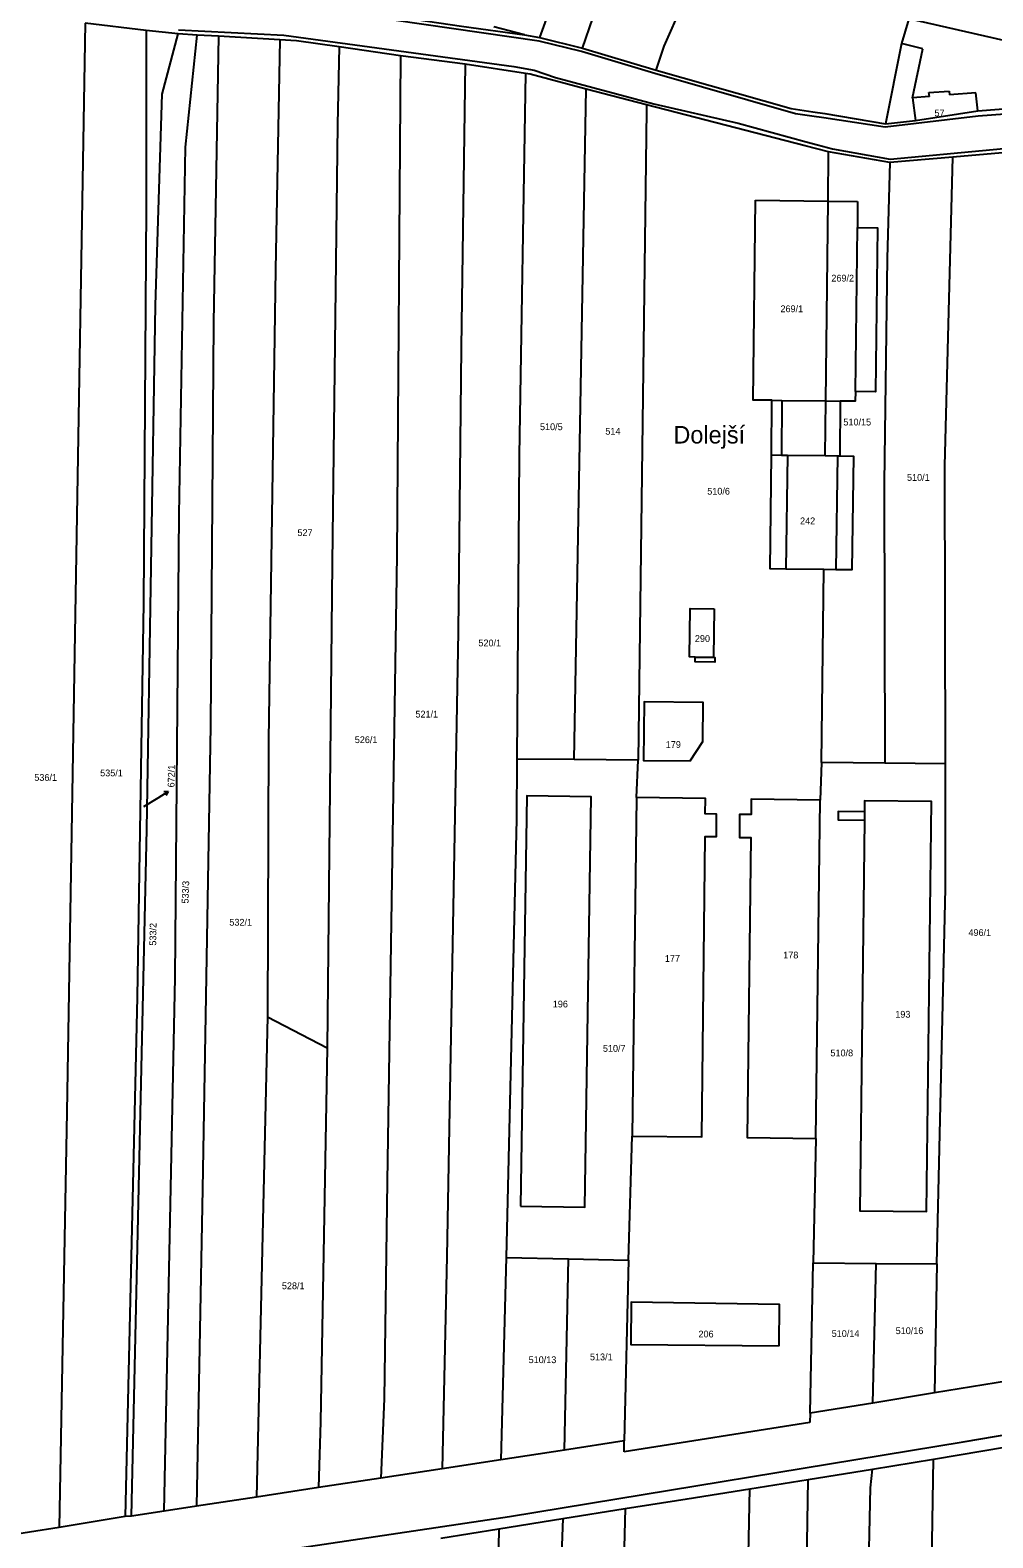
# Model space of a CAD drawing. Extents: x -7483133 to -743169, y -11317770 to -1127091.
# Drawn here: x -746642.5 to -746401, y -1132680.7 to -1132302.3 of the extents above; entities that cross this region are included whole.
import ezdxf

# ---------------------------------------------------------------- set-up
doc = ezdxf.new("R2010")
doc.units = 0
for name, color, linetype in [('Hranice parcel', 7, 'Continuous'), ('Parcelní čísla', 7, 'Continuous'), ('Pop  PČ popisy', 7, 'Continuous'), ('Vnitřní kresba', 7, 'Continuous')]:
    doc.layers.add(name, color=color, linetype=linetype)

msp = doc.modelspace()

# ---------------------------------------------------------------- linework, layer by layer
at = {"layer": 'Hranice parcel'}
for p, q in [((-746503.94, -1132306.81), (-746501.31, -1132299.32)), ((-746398.2, -1132304.9), (-746422.09, -1132299.47)), ((-746613.37, -1132302.42), (-746628.68, -1132300.58)), ((-746605.37, -1132303.28), (-746613.37, -1132302.42)), ((-746600.59, -1132303.55), (-746605.37, -1132303.28)), ((-746518.52, -1132303.5), (-746526.21, -1132301.5)), ((-746518.52, -1132303.5), (-746514.75, -1132304.17)), ((-746595.23, -1132303.86), (-746600.59, -1132303.55)), ((-746579.9, -1132304.75), (-746595.23, -1132303.86)), ((-746549.55, -1132308.74), (-746564.99, -1132306.52)), ((-746514.75, -1132304.17), (-746503.94, -1132306.81)), ((-746503.94, -1132306.81), (-746485.44, -1132312.39)), ((-746533.39, -1132310.87), (-746549.55, -1132308.74)), ((-746518.2, -1132313.24), (-746533.39, -1132310.87)), ((-746506, -1132485.37), (-746503.02, -1132317.1)), ((-746487.88, -1132321.09), (-746503.02, -1132317.1)), ((-746487.88, -1132321.09), (-746487.9, -1132322.49)), ((-746448.07, -1132331.38), (-746487.88, -1132321.09)), ((-746487.9, -1132322.49), (-746489.99, -1132485.51)), ((-746445.16, -1132332.13), (-746448.07, -1132331.38)), ((-746442.17, -1132332.88), (-746445.16, -1132332.13)), ((-746442.31, -1132345.22), (-746442.17, -1132332.88)), ((-746426.85, -1132335.55), (-746442.17, -1132332.88)), ((-746392.82, -1132332.59), (-746411.01, -1132334.18)), ((-746411.01, -1132334.18), (-746426.85, -1132335.55)), ((-746460.56, -1132344.98), (-746442.31, -1132345.22)), ((-746442.31, -1132345.22), (-746434.93, -1132345.32)), ((-746452.53, -1132408.97), (-746443.06, -1132409.09)), ((-746443.06, -1132409.09), (-746439.94, -1132409.14)), ((-746439.94, -1132409.14), (-746439.38, -1132409.16)), ((-746443.39, -1132437.7), (-746452.91, -1132437.58)), ((-746443.96, -1132486.07), (-746443.39, -1132437.7)), ((-746440.33, -1132437.74), (-746443.39, -1132437.7)), ((-746506, -1132485.37), (-746520.37, -1132485.24)), ((-746489.99, -1132485.51), (-746506, -1132485.37)), ((-746490.36, -1132494.89), (-746489.99, -1132485.51)), ((-746443.96, -1132486.07), (-746444.3, -1132495.53)), ((-746428.08, -1132486.27), (-746443.96, -1132486.07)), ((-746412.82, -1132486.47), (-746428.08, -1132486.27)), ((-746490.36, -1132494.89), (-746491.44, -1132579.84)), ((-746445.35, -1132580.44), (-746444.3, -1132495.53)), ((-746582.99, -1132549.96), (-746585.75, -1132670.43)), ((-746582.99, -1132549.96), (-746568.01, -1132557.67)), ((-746492.38, -1132610.98), (-746491.44, -1132579.84)), ((-746445.35, -1132580.44), (-746446.07, -1132611.66)), ((-746523.05, -1132610.33), (-746524.45, -1132661.07)), ((-746523.05, -1132610.33), (-746507.48, -1132610.66)), ((-746508.44, -1132658.63), (-746507.48, -1132610.66)), ((-746507.48, -1132610.66), (-746492.38, -1132610.98)), ((-746492.38, -1132610.98), (-746493.45, -1132656.34)), ((-746446.82, -1132649.4), (-746446.07, -1132611.66)), ((-746446.07, -1132611.66), (-746430.26, -1132611.8)), ((-746431.12, -1132646.84), (-746430.26, -1132611.8)), ((-746430.26, -1132611.8), (-746415.02, -1132611.93)), ((-746415.02, -1132611.93), (-746415.63, -1132644.31)), ((-746397.09, -1132641.29), (-746415.63, -1132644.31)), ((-746431.12, -1132646.84), (-746446.82, -1132649.4)), ((-746415.63, -1132644.31), (-746431.12, -1132646.84)), ((-746446.82, -1132649.4), (-746446.87, -1132651.69)), ((-746446.87, -1132651.69), (-746493.51, -1132659.07)), ((-746508.44, -1132658.63), (-746524.45, -1132661.07)), ((-746493.45, -1132656.34), (-746508.44, -1132658.63)), ((-746493.51, -1132659.07), (-746493.45, -1132656.34)), ((-746415.89, -1132660.88), (-746397.52, -1132657.82)), ((-746524.45, -1132661.07), (-746539.11, -1132663.31)), ((-746431.15, -1132663.43), (-746415.89, -1132660.88)), ((-746554.56, -1132665.67), (-746570.19, -1132668.05)), ((-746539.11, -1132663.31), (-746554.56, -1132665.67)), ((-746461.92, -1132668.34), (-746447.3, -1132666.01)), ((-746447.3, -1132666.01), (-746431.15, -1132663.43)), ((-746585.75, -1132670.43), (-746600.75, -1132672.72)), ((-746570.19, -1132668.05), (-746585.75, -1132670.43)), ((-746608.92, -1132673.97), (-746617.07, -1132675.21)), ((-746600.75, -1132672.72), (-746608.92, -1132673.97)), ((-746508.88, -1132675.84), (-746493.19, -1132673.33)), ((-746635.22, -1132678.03), (-746650.17, -1132680.45)), ((-746618.65, -1132675.35), (-746635.22, -1132678.03)), ((-746617.07, -1132675.21), (-746618.65, -1132675.35)), ((-746524.93, -1132678.4), (-746508.88, -1132675.84)), ((-746508.88, -1132675.84), (-746511.87, -1132753.93)), ((-746539.48, -1132680.72), (-746524.93, -1132678.4))]:
    msp.add_line(p, q, dxfattribs=at)
for points in [[(-746504.41, -1132275.72), (-746509.03, -1132288.43), (-746514.75, -1132304.17)], [(-746485.44, -1132312.39), (-746483.4, -1132306.31), (-746474.28, -1132285.54)], [(-746572.31, -1132295.81), (-746562.17, -1132297.22), (-746534.28, -1132301.35), (-746518.52, -1132303.5)], [(-746422.09, -1132299.47), (-746423.86, -1132305.66), (-746427.94, -1132325.8)], [(-746628.68, -1132300.58), (-746631.28, -1132453.79), (-746633.28, -1132573.72), (-746635.22, -1132678.03)], [(-746613.37, -1132302.42), (-746613.37, -1132346.68), (-746614.08, -1132446.06), (-746615.66, -1132545), (-746618.65, -1132675.35)], [(-746617.07, -1132675.21), (-746613.21, -1132502.87), (-746611.08, -1132371.37), (-746609.37, -1132318.4), (-746605.37, -1132303.28)], [(-746608.92, -1132673.97), (-746606.11, -1132540.09), (-746605.1, -1132423.88), (-746603.53, -1132331.66), (-746600.59, -1132303.55)], [(-746595.23, -1132303.86), (-746596.54, -1132375.65), (-746597.26, -1132477.01), (-746599.26, -1132593.08), (-746600.75, -1132672.72)], [(-746579.9, -1132304.75), (-746580.99, -1132362.37), (-746582.7, -1132480.44), (-746582.99, -1132549.96)], [(-746564.99, -1132306.52), (-746575.68, -1132304.99), (-746579.9, -1132304.75)], [(-746564.99, -1132306.52), (-746565.43, -1132325.98), (-746566.71, -1132436.04), (-746568.01, -1132557.67)], [(-746549.55, -1132308.74), (-746550.51, -1132434.05), (-746552.94, -1132591.21), (-746553.66, -1132645.75), (-746554.56, -1132665.67)], [(-746533.39, -1132310.87), (-746534.4, -1132381.92), (-746535.13, -1132453.3), (-746537.98, -1132610.05), (-746539.11, -1132663.31)], [(-746518.2, -1132313.24), (-746519.81, -1132409.04), (-746520.37, -1132485.24)], [(-746503.02, -1132317.1), (-746517.02, -1132313.41), (-746518.2, -1132313.24)], [(-746485.44, -1132312.39), (-746451.58, -1132322.02), (-746446.14, -1132322.78), (-746443.16, -1132323.2), (-746427.94, -1132325.8)], [(-746427.94, -1132325.8), (-746420.34, -1132325.03), (-746404.78, -1132322.59), (-746395.13, -1132321.84)], [(-746426.85, -1132335.55), (-746427.53, -1132359.53), (-746428.24, -1132415.89), (-746428.08, -1132486.27)], [(-746412.82, -1132486.47), (-746413.02, -1132411.65), (-746411.01, -1132334.18)], [(-746456.52, -1132408.91), (-746456.45, -1132395.21), (-746461.15, -1132395.16), (-746460.56, -1132344.98)], [(-746443.06, -1132409.09), (-746442.9, -1132395.38), (-746442.31, -1132345.22)], [(-746434.93, -1132345.32), (-746434.96, -1132351.85), (-746429.89, -1132351.96), (-746430.39, -1132393.08), (-746435.47, -1132393.02), (-746435.54, -1132395.46), (-746439.24, -1132395.43), (-746439.38, -1132409.16)], [(-746452.91, -1132437.58), (-746456.87, -1132437.46), (-746456.52, -1132408.91)], [(-746456.52, -1132408.91), (-746453.98, -1132408.95), (-746452.53, -1132408.97)], [(-746439.38, -1132409.16), (-746435.95, -1132409.27), (-746436.34, -1132437.75), (-746440.33, -1132437.74)], [(-746470.9, -1132447.53), (-746471.04, -1132459.69), (-746470.74, -1132459.72), (-746470.7, -1132460.94), (-746475.69, -1132460.82), (-746475.68, -1132459.65), (-746477.09, -1132459.62), (-746476.95, -1132447.46), (-746470.9, -1132447.53)], [(-746476.94, -1132485.69), (-746473.77, -1132480.86), (-746473.64, -1132471.05), (-746488.48, -1132470.84), (-746488.65, -1132485.59), (-746476.94, -1132485.69)], [(-746520.37, -1132485.24), (-746520.49, -1132500.34), (-746523.05, -1132610.33)], [(-746415.02, -1132611.93), (-746412.87, -1132517.7), (-746412.82, -1132486.47)], [(-746519.46, -1132597.46), (-746503.32, -1132597.69), (-746501.74, -1132494.74), (-746517.87, -1132494.47), (-746519.46, -1132597.46)], [(-746491.44, -1132579.84), (-746474.02, -1132580.06), (-746473.18, -1132504.68), (-746470.3, -1132504.71), (-746470.29, -1132499.03), (-746473.11, -1132499), (-746473.07, -1132495.14), (-746490.36, -1132494.89)], [(-746444.3, -1132495.53), (-746461.6, -1132495.32), (-746461.63, -1132499.17), (-746464.54, -1132499.14), (-746464.56, -1132504.89), (-746461.68, -1132504.91), (-746462.63, -1132580.24), (-746445.35, -1132580.44)], [(-746433.2, -1132500.57), (-746434.38, -1132598.64), (-746417.62, -1132598.8), (-746416.34, -1132495.88), (-746433.14, -1132495.69), (-746433.17, -1132498.48), (-746439.8, -1132498.4), (-746439.79, -1132500.49), (-746433.2, -1132500.57)], [(-746568.01, -1132557.67), (-746569.62, -1132651.54), (-746570.19, -1132668.05)], [(-746454.62, -1132632.47), (-746454.48, -1132622.1), (-746491.75, -1132621.52), (-746491.83, -1132632.12), (-746454.62, -1132632.47)], [(-746898.28, -1132733.66), (-746836.86, -1132723.53), (-746713.33, -1132704.19), (-746619.13, -1132689.77), (-746522.21, -1132675.28), (-746408.39, -1132656.58), (-746328.84, -1132643.04)], [(-746423.66, -1133042.13), (-746422.21, -1133031.75), (-746419.43, -1132870.16), (-746417.02, -1132733.26), (-746415.89, -1132660.88)], [(-746454.93, -1133037.84), (-746453.95, -1133027.27), (-746451.93, -1132935.37), (-746451.41, -1132924.92), (-746449.85, -1132830.84), (-746448.56, -1132744.9), (-746447.3, -1132666.01)], [(-746438.18, -1133040.13), (-746437.53, -1133033.27), (-746436.57, -1132940.05), (-746432.87, -1132769.03), (-746432.24, -1132694.84), (-746431.66, -1132668.15), (-746431.15, -1132663.43)], [(-746493.19, -1132673.33), (-746477.65, -1132670.85), (-746461.92, -1132668.34)], [(-746469.94, -1133035.78), (-746468.91, -1133024.02), (-746466.91, -1132934.23), (-746464.06, -1132771.35), (-746461.92, -1132668.34)], [(-746493.19, -1132673.33), (-746494.03, -1132705.97), (-746496.17, -1132762.5), (-746496.03, -1132785.34)], [(-746524.93, -1132678.4), (-746525.58, -1132714.77), (-746525.93, -1132727.41), (-746526.72, -1132747.96)]]:
    msp.add_lwpolyline(points, dxfattribs=at)
at = {"layer": 'Pop  PČ popisy'}
for p, q in [((-746613.98, -1132497.11), (-746610.41, -1132494.95)), ((-746610.41, -1132494.95), (-746607.84, -1132493.4)), ((-746607.84, -1132493.4), (-746608.95, -1132493.49)), ((-746607.84, -1132493.4), (-746608.44, -1132494.35))]:
    msp.add_line(p, q, dxfattribs=at)
at = {"layer": 'Vnitřní kresba'}
for p, q in [((-746514.76, -1132305.1), (-746572.69, -1132296.69)), ((-746605.32, -1132302.23), (-746578.84, -1132303.61)), ((-746578.84, -1132303.61), (-746521.19, -1132311.48)), ((-746504.14, -1132307.72), (-746514.76, -1132305.1)), ((-746418.57, -1132307), (-746423.86, -1132305.66)), ((-746421.11, -1132319.3), (-746418.57, -1132307)), ((-746485.8, -1132313.24), (-746504.14, -1132307.72)), ((-746521.19, -1132311.48), (-746516.04, -1132312.33)), ((-746516.04, -1132312.33), (-746510.71, -1132314.23)), ((-746510.71, -1132314.23), (-746485.99, -1132320.82)), ((-746450.49, -1132323.31), (-746485.8, -1132313.24)), ((-746417, -1132318.01), (-746411.93, -1132317.65)), ((-746416.89, -1132318.97), (-746417, -1132318.01)), ((-746411.93, -1132317.65), (-746411.81, -1132318.58)), ((-746405.28, -1132318.08), (-746411.81, -1132318.58)), ((-746404.78, -1132322.59), (-746405.28, -1132318.08)), ((-746485.99, -1132320.82), (-746464.89, -1132325.65)), ((-746416.89, -1132318.97), (-746421.11, -1132319.3)), ((-746421.11, -1132319.3), (-746420.34, -1132325.03)), ((-746380.7, -1132322.22), (-746404.7, -1132323.87)), ((-746464.89, -1132325.65), (-746447.83, -1132330.31)), ((-746446.39, -1132323.91), (-746450.49, -1132323.31)), ((-746443.42, -1132324.35), (-746446.39, -1132323.91)), ((-746428.01, -1132326.63), (-746443.42, -1132324.35)), ((-746404.7, -1132323.87), (-746428.01, -1132326.63)), ((-746447.83, -1132330.31), (-746444.93, -1132331.1)), ((-746444.93, -1132331.1), (-746441.17, -1132332.13)), ((-746441.17, -1132332.13), (-746426.75, -1132334.69)), ((-746426.75, -1132334.69), (-746395.58, -1132331.79)), ((-746435.47, -1132393.02), (-746434.96, -1132351.85)), ((-746456.45, -1132395.21), (-746453.88, -1132395.24)), ((-746453.88, -1132395.24), (-746453.98, -1132408.95)), ((-746453.88, -1132395.24), (-746442.9, -1132395.38)), ((-746442.9, -1132395.38), (-746439.24, -1132395.43)), ((-746452.53, -1132408.97), (-746452.91, -1132437.58)), ((-746439.94, -1132409.14), (-746440.33, -1132437.74)), ((-746475.68, -1132459.65), (-746471.04, -1132459.69)), ((-746433.17, -1132498.48), (-746433.2, -1132500.57))]:
    msp.add_line(p, q, dxfattribs=at)

# ---------------------------------------------------------------- texts
at = {"layer": 'Parcelní čísla'}
for s, p in [('57', (-746415.62, -1132323.97)), ('269/2', (-746441.49, -1132365.41)), ('269/1', (-746454.26, -1132373.1)), ('510/5', (-746514.59, -1132402.7)), ('510/15', (-746438.47, -1132401.53)), ('514', (-746498.2, -1132403.84)), ('510/1', (-746422.51, -1132415.42)), ('510/6', (-746472.63, -1132418.88)), ('527', (-746575.44, -1132429.27)), ('242', (-746449.34, -1132426.32)), ('290', (-746475.73, -1132455.84)), ('520/1', (-746530.04, -1132456.95)), ('521/1', (-746545.84, -1132474.82)), ('526/1', (-746561.06, -1132481.23)), ('179', (-746483.04, -1132482.44)), ('535/1', (-746624.94, -1132489.57)), ('536/1', (-746641.46, -1132490.71)), ('532/1', (-746592.53, -1132527.04)), ('496/1', (-746407.1, -1132529.63)), ('178', (-746453.57, -1132535.27)), ('177', (-746483.26, -1132536.13)), ('196', (-746511.38, -1132547.56)), ('193', (-746425.45, -1132550.13)), ('510/7', (-746498.81, -1132558.69)), ('510/8', (-746441.72, -1132559.83)), ('528/1', (-746579.35, -1132618.27)), ('206', (-746474.83, -1132630.37)), ('510/14', (-746441.41, -1132630.25)), ('510/16', (-746425.36, -1132629.54)), ('510/13', (-746517.45, -1132636.82)), ('513/1', (-746502.06, -1132636.11))]:
    msp.add_text(s, height=1.7, dxfattribs=at).set_placement(p)
for s, rotation, p in [('672/1', 89, (-746606.3, -1132492.36)), ('533/3', 88, (-746602.79, -1132521.52)), ('533/2', 89, (-746610.89, -1132532.07))]:
    msp.add_text(s, height=1.7, rotation=rotation, dxfattribs=at).set_placement(p)
at = {"layer": 'Pop  PČ popisy'}
msp.add_text('Dolejší', height=4.4, dxfattribs=at).set_placement((-746481.12, -1132406.05))

doc.saveas('drawing.dxf')
